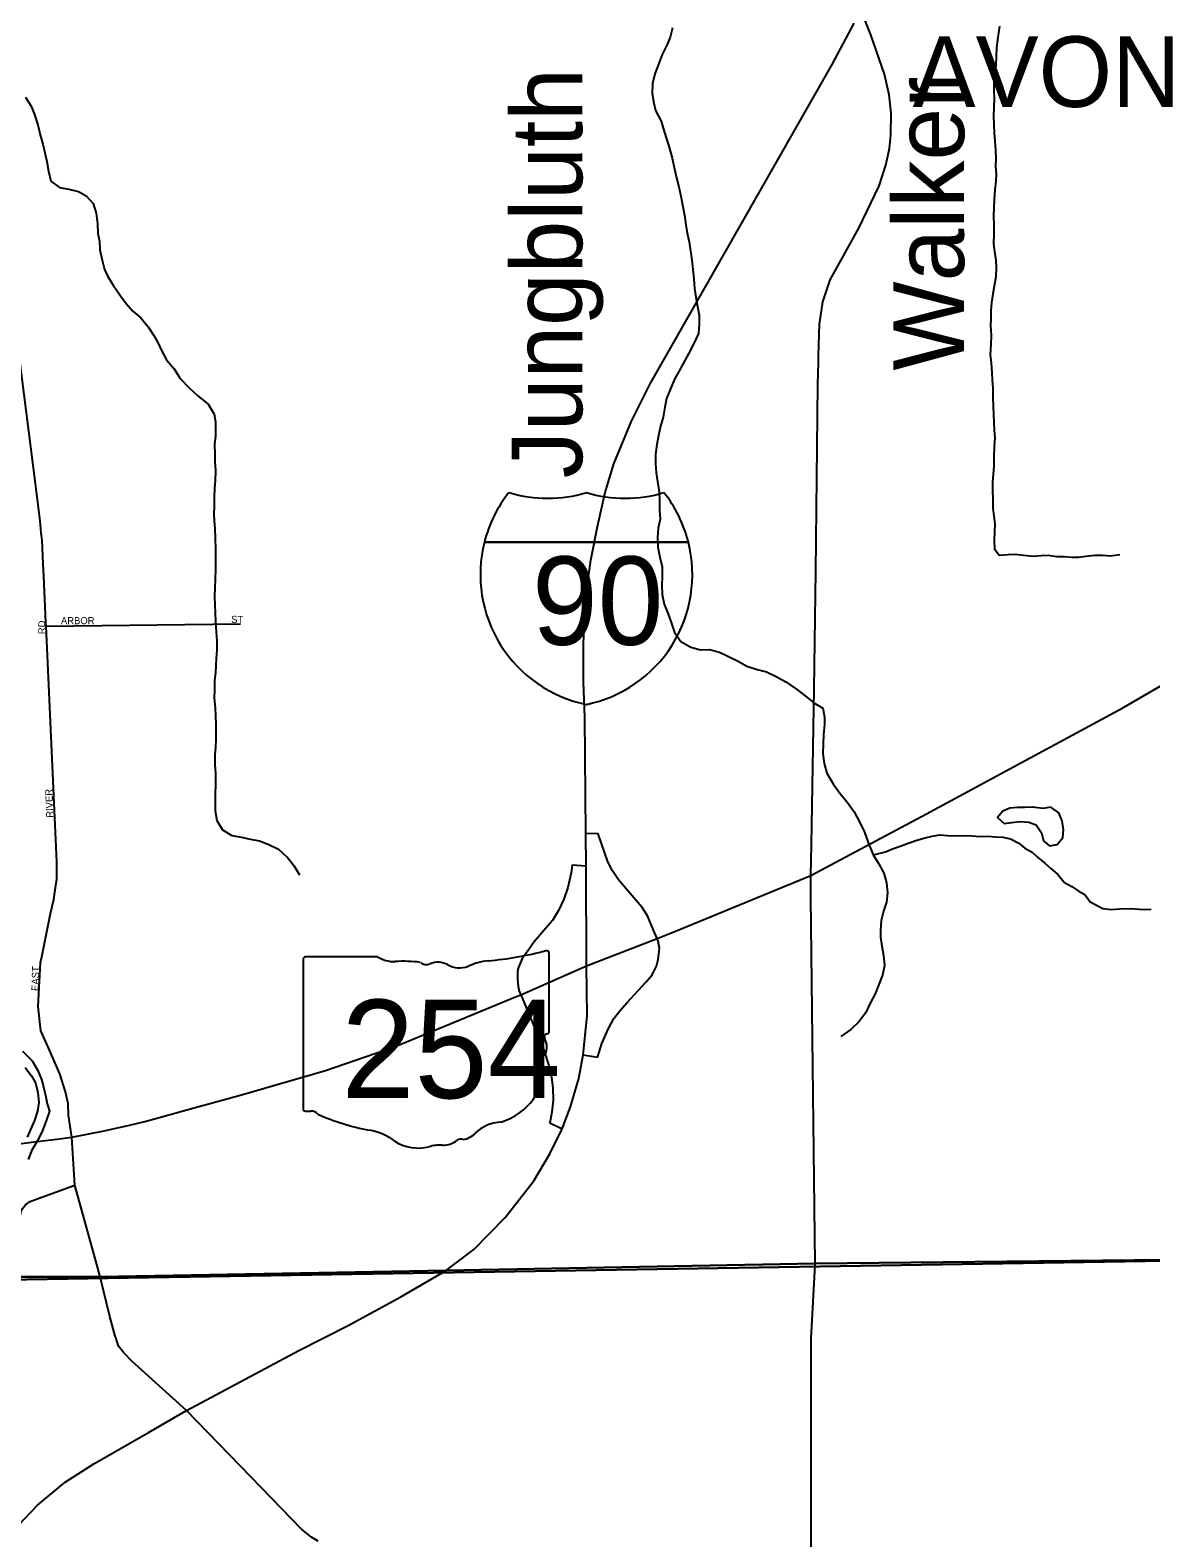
# Model space of a CAD drawing. Extents: x 1857828 to 2277390, y 930619 to 1324581.
# Drawn here: x 2078983 to 2086916, y 1243739 to 1254407 of the extents above; entities that cross this region are included whole.
import ezdxf

# ---------------------------------------------------------------- set-up
doc = ezdxf.new("R2010")
doc.units = 0
for name, color, linetype in [('GM_X_City_Street', 7, 'Continuous'), ('GM_X_City_Street_Text', 7, 'Continuous'), ('GM_X_Corporation', 7, 'Continuous'), ('GM_X_Corporation_Text', 7, 'Continuous'), ('GM_X_Interchange_Ramps', 7, 'Continuous'), ('GM_X_Interstate_Location', 7, 'Continuous'), ('GM_X_Interstate_Route', 7, 'Continuous'), ('GM_X_Interstate_Shield', 7, 'Continuous'), ('GM_X_Major_River', 7, 'Continuous'), ('GM_X_Minor_Lake', 7, 'Continuous'), ('GM_X_Minor_River', 7, 'Continuous'), ('GM_X_Minor_River_Text', 7, 'Continuous'), ('GM_X_State_Location', 7, 'Continuous'), ('GM_X_State_Route', 7, 'Continuous'), ('GM_X_State_Shield', 7, 'Continuous'), ('GM_X_Township', 7, 'Continuous')]:
    doc.layers.add(name, color=color, linetype=linetype)

msp = doc.modelspace()

# ---------------------------------------------------------------- linework, layer by layer
at = {"layer": 'GM_X_City_Street'}
for points in [[(2079066, 1247850), (2079128, 1248157), (2079150, 1248255), (2079156, 1248291), (2079161, 1248323), (2079165, 1248356), (2079171, 1248400), (2079171, 1248522), (2079096, 1250190), (2079094, 1250216), (2079085, 1250435), (2079081, 1250544), (2079076, 1250630), (2079070, 1250742), (2079068, 1250799), (2079061, 1250851), (2079053, 1250935), (2079024, 1251180), (2078679, 1253867)], [(2079096, 1250190), (2080473, 1250206)], [(2079278, 1246575), (2079254, 1246729), (2079251, 1246812), (2079233, 1246894), (2079192, 1247021), (2079113, 1247205), (2079058, 1247327), (2079040, 1247499), (2079057, 1247809), (2079066, 1247850)], [(2079454, 1245674), (2079299, 1246235), (2079278, 1246575)], [(2078772, 1245558), (2078782, 1245586), (2078812, 1245672), (2078854, 1245786), (2078868, 1245830), (2078881, 1245873), (2078898, 1245949), (2078909, 1246005), (2078920, 1246049), (2078928, 1246069), (2078950, 1246095), (2078983, 1246119), (2079033, 1246138), (2079299, 1246235)], [(2079589, 1245157), (2079586, 1245166), (2079546, 1245304), (2079478, 1245586), (2079454, 1245674)], [(2080548, 1244168), (2080090, 1244639), (2079703, 1244989), (2079646, 1245047), (2079609, 1245094), (2079589, 1245157)], [(2081023, 1243715), (2080975, 1243744), (2080904, 1243800), (2080548, 1244168)]]:
    msp.add_lwpolyline(points, dxfattribs=at)
at = {"layer": 'GM_X_Corporation'}
for points in [[(2073290, 1243422), (2073012, 1245464), (2077086, 1245535), (2087019, 1245699)], [(2087019, 1245699), (2077086, 1245535)]]:
    msp.add_lwpolyline(points, dxfattribs=at)
at = {"layer": 'GM_X_Interchange_Ramps'}
for points in [[(2083421, 1247979), (2083402, 1248023), (2083354, 1248141), (2083316, 1248199), (2083270, 1248252), (2083147, 1248396), (2083106, 1248458), (2083072, 1248523), (2083005, 1248721), (2082916, 1248723)], [(2082918, 1248492), (2082819, 1248498), (2082812, 1248444), (2082790, 1248341), (2082761, 1248257), (2082723, 1248179), (2082680, 1248107), (2082620, 1248036), (2082552, 1247956), (2082501, 1247886), (2082466, 1247838), (2082437, 1247770), (2082432, 1247743), (2082433, 1247694), (2082438, 1247639), (2082445, 1247608), (2082456, 1247582)], [(2082898, 1247157), (2082999, 1247140), (2083001, 1247145), (2083031, 1247236), (2083078, 1247342), (2083115, 1247413), (2083157, 1247469), (2083209, 1247528), (2083343, 1247672), (2083386, 1247722), (2083417, 1247785), (2083428, 1247831), (2083434, 1247872), (2083437, 1247910), (2083428, 1247961), (2083421, 1247979)], [(2082456, 1247582), (2082465, 1247559), (2082620, 1247189), (2082655, 1247080), (2082674, 1246997), (2082683, 1246923), (2082686, 1246835), (2082677, 1246750), (2082662, 1246675), (2082748, 1246634)]]:
    msp.add_lwpolyline(points, dxfattribs=at)
at = {"layer": 'GM_X_Interstate_Route'}
for points in [[(2082922, 1247787), (2082918, 1248492), (2082916, 1248723), (2082910, 1249544), (2082901, 1249796), (2082901, 1250038), (2082906, 1250255), (2082925, 1250471), (2082953, 1250657), (2082999, 1250895), (2083054, 1251136), (2083115, 1251339), (2083240, 1251640), (2083373, 1251905), (2084661, 1254164), (2084817, 1254456)], [(2081931, 1245634), (2082123, 1245778), (2082345, 1246005), (2082548, 1246265), (2082662, 1246455), (2082748, 1246634), (2082809, 1246788), (2082866, 1246988), (2082898, 1247157), (2082925, 1247432), (2082922, 1247787)], [(2080090, 1244639), (2080886, 1245065), (2081234, 1245242), (2081606, 1245443), (2081927, 1245631), (2081931, 1245634)], [(2078147, 1242480), (2078285, 1242776), (2078548, 1243357), (2078667, 1243527), (2078771, 1243668), (2078895, 1243824), (2079034, 1243971), (2079230, 1244132), (2079434, 1244263), (2079820, 1244484), (2080090, 1244639)]]:
    msp.add_lwpolyline(points, dxfattribs=at)
at = {"layer": 'GM_X_Interstate_Shield'}
for p, q in [((2082199, 1250785), (2083642, 1250785)), ((2083642, 1250785), (2082199, 1250785)), ((2083642, 1250785), (2082199, 1250785))]:
    msp.add_line(p, q, dxfattribs=at)
for centre, start, end in [((2083108, 1250555), 141.669, 165.8066), ((2082647, 1252033), 253.0091, 286.9909), ((2083195, 1252033), 253.0091, 286.9909), ((2082733, 1250555), 14.1934, 38.331), ((2083108, 1250555), 165.8066, 258.463), ((2082733, 1250555), 281.537, 14.1934)]:
    msp.add_arc(centre, 938, start, end, dxfattribs=at)
at = {"layer": 'GM_X_Major_River'}
for points in [[(2078929, 1247183), (2078998, 1247115), (2079038, 1247046), (2079063, 1246982), (2079077, 1246930), (2079093, 1246860), (2079104, 1246809), (2079120, 1246759), (2079096, 1246689), (2079070, 1246620), (2079038, 1246552), (2078996, 1246481), (2078970, 1246417)], [(2078948, 1247068), (2078992, 1247008), (2079021, 1246958), (2079037, 1246890), (2079045, 1246819), (2079035, 1246759), (2079014, 1246691), (2078986, 1246628), (2078962, 1246574)]]:
    msp.add_lwpolyline(points, dxfattribs=at)
at = {"layer": 'GM_X_Minor_Lake'}
for points in [[(2086077, 1248909), (2086022, 1248906), (2085972, 1248906), (2085918, 1248901), (2085868, 1248880), (2085832, 1248836), (2085877, 1248794), (2085931, 1248801), (2085991, 1248808), (2086053, 1248804), (2086104, 1248785)], [(2086080, 1248909), (2086022, 1248906), (2085972, 1248906), (2085918, 1248901), (2085868, 1248880), (2085832, 1248836), (2085877, 1248794), (2085931, 1248801), (2085991, 1248808), (2086053, 1248804), (2086104, 1248785)], [(2086104, 1248785), (2086143, 1248727), (2086157, 1248671), (2086200, 1248635), (2086254, 1248644), (2086294, 1248694), (2086297, 1248749), (2086288, 1248813), (2086264, 1248869), (2086209, 1248908), (2086155, 1248900), (2086077, 1248909)], [(2086104, 1248785), (2086143, 1248727), (2086157, 1248671), (2086200, 1248635), (2086254, 1248644), (2086294, 1248694), (2086297, 1248749), (2086288, 1248813), (2086264, 1248869), (2086209, 1248908), (2086155, 1248900), (2086077, 1248909)]]:
    msp.add_lwpolyline(points, dxfattribs=at)
at = {"layer": 'GM_X_Minor_River'}
for points in [[(2083531, 1254424), (2083513, 1254357), (2083493, 1254307), (2083457, 1254236), (2083428, 1254160), (2083404, 1254098), (2083388, 1254029), (2083386, 1253959), (2083397, 1253891), (2083411, 1253838), (2083451, 1253764), (2083464, 1253714), (2083508, 1253569), (2083527, 1253501), (2083543, 1253435), (2083559, 1253362), (2083576, 1253298), (2083590, 1253232), (2083600, 1253172), (2083615, 1253099), (2083625, 1253031), (2083635, 1252971), (2083648, 1252909), (2083668, 1252780), (2083681, 1252647), (2083685, 1252579), (2083695, 1252519), (2083706, 1252452), (2083718, 1252390), (2083720, 1252326), (2083714, 1252262), (2083682, 1252191), (2083645, 1252121), (2083573, 1251988), (2083545, 1251937), (2083515, 1251869), (2083487, 1251800), (2083475, 1251740), (2083464, 1251670), (2083446, 1251605), (2083432, 1251539), (2083420, 1251475)], [(2085845, 1254436), (2085830, 1254342), (2085823, 1254281), (2085821, 1254223), (2085818, 1254159), (2085813, 1254090), (2085805, 1254036), (2085804, 1253980), (2085807, 1253925), (2085804, 1253859), (2085802, 1253801), (2085805, 1253738), (2085808, 1253682), (2085812, 1253622), (2085817, 1253556), (2085820, 1253501), (2085817, 1253443), (2085821, 1253389), (2085820, 1253339), (2085813, 1253278), (2085807, 1253210), (2085806, 1253151), (2085803, 1253095), (2085804, 1253025), (2085806, 1252963), (2085803, 1252896), (2085810, 1252842), (2085819, 1252778), (2085821, 1252727), (2085820, 1252663), (2085807, 1252595), (2085797, 1252542), (2085788, 1252480), (2085783, 1252422), (2085783, 1252365), (2085782, 1252315), (2085785, 1252249), (2085784, 1252184), (2085780, 1252110), (2085785, 1252054), (2085790, 1251983), (2085793, 1251931), (2085797, 1251877), (2085798, 1251809), (2085801, 1251742), (2085802, 1251690), (2085804, 1251628), (2085807, 1251577), (2085812, 1251523), (2085808, 1251461), (2085805, 1251386), (2085804, 1251320), (2085799, 1251266), (2085795, 1251212), (2085796, 1251149), (2085797, 1251091), (2085798, 1251025), (2085804, 1250968), (2085811, 1250914), (2085810, 1250860), (2085808, 1250798), (2085809, 1250737), (2085842, 1250693), (2085906, 1250698), (2085956, 1250699), (2086015, 1250693), (2086083, 1250686), (2086139, 1250691), (2086191, 1250693), (2086250, 1250684), (2086304, 1250684), (2086354, 1250679), (2086404, 1250678), (2086457, 1250686)], [(2078951, 1253934), (2078991, 1253870), (2079014, 1253810), (2079038, 1253738), (2079054, 1253667), (2079073, 1253601), (2079089, 1253529), (2079101, 1253477), (2079114, 1253410), (2079130, 1253338), (2079190, 1253294), (2079257, 1253282), (2079325, 1253266), (2079380, 1253236), (2079430, 1253180), (2079450, 1253112), (2079459, 1253038), (2079463, 1252969), (2079475, 1252915), (2079477, 1252853), (2079492, 1252780), (2079510, 1252714), (2079532, 1252664), (2079571, 1252602), (2079623, 1252528), (2079662, 1252473), (2079710, 1252419), (2079767, 1252371), (2079819, 1252309), (2079858, 1252247), (2079886, 1252197), (2079914, 1252141), (2079949, 1252074), (2080003, 1252010), (2080046, 1251942), (2080108, 1251876), (2080171, 1251820), (2080243, 1251760), (2080286, 1251689), (2080296, 1251637), (2080296, 1251587), (2080294, 1251531), (2080288, 1251478), (2080291, 1251408), (2080291, 1251358), (2080295, 1251290), (2080293, 1251221), (2080288, 1251167), (2080286, 1251103), (2080286, 1251036), (2080284, 1250986), (2080285, 1250936), (2080291, 1250881), (2080293, 1250809), (2080295, 1250741), (2080296, 1250592), (2080292, 1250524), (2080290, 1250459), (2080289, 1250403), (2080291, 1250337), (2080293, 1250284), (2080295, 1250218), (2080300, 1250150), (2080304, 1250084), (2080304, 1250019), (2080300, 1249963), (2080297, 1249911), (2080295, 1249860), (2080289, 1249806), (2080287, 1249740), (2080285, 1249683), (2080292, 1249611), (2080294, 1249555), (2080298, 1249491), (2080298, 1249438), (2080297, 1249388), (2080295, 1249332), (2080291, 1249282), (2080291, 1249213), (2080294, 1249145), (2080296, 1249072), (2080292, 1249002), (2080292, 1248950), (2080293, 1248884), (2080305, 1248815), (2080345, 1248749), (2080410, 1248709), (2080480, 1248697), (2080540, 1248683), (2080607, 1248672), (2080673, 1248646), (2080740, 1248612), (2080806, 1248550), (2080849, 1248497)], [(2083420, 1251475), (2083410, 1251408), (2083409, 1251340), (2083415, 1251276), (2083425, 1251213), (2083436, 1251141), (2083438, 1251075), (2083438, 1251008), (2083442, 1250946), (2083428, 1250884), (2083423, 1250817), (2083427, 1250749), (2083441, 1250679), (2083458, 1250610), (2083458, 1250544), (2083454, 1250478), (2083456, 1250414), (2083471, 1250345), (2083497, 1250281), (2083520, 1250215), (2083544, 1250146), (2083588, 1250082), (2083659, 1250042), (2083729, 1250022), (2083789, 1250025), (2083862, 1250007), (2083995, 1249943), (2084057, 1249907), (2084129, 1249883), (2084196, 1249867), (2084264, 1249833), (2084333, 1249795), (2084409, 1249745), (2084470, 1249697), (2084530, 1249647), (2084595, 1249609), (2084605, 1249545), (2084605, 1249495), (2084599, 1249424), (2084596, 1249356), (2084594, 1249290), (2084604, 1249219), (2084623, 1249149), (2084667, 1249075), (2084715, 1249009), (2084768, 1248941), (2084816, 1248876), (2084855, 1248806), (2084889, 1248732), (2084916, 1248660)], [(2086457, 1250686), (2086519, 1250693), (2086577, 1250692), (2086629, 1250688), (2086696, 1250697)], [(2084951, 1248571), (2084971, 1248577), (2085039, 1248592), (2085087, 1248614), (2085149, 1248635), (2085205, 1248656), (2085259, 1248675), (2085319, 1248691), (2085369, 1248704), (2085422, 1248713), (2085478, 1248709), (2085530, 1248706), (2085588, 1248709), (2085651, 1248707), (2085709, 1248702), (2085763, 1248704), (2085816, 1248699), (2085868, 1248698), (2085924, 1248684), (2085981, 1248655), (2086025, 1248619), (2086076, 1248591), (2086113, 1248556), (2086167, 1248512), (2086208, 1248476), (2086255, 1248435), (2086306, 1248377), (2086356, 1248347), (2086401, 1248318), (2086449, 1248290), (2086486, 1248240), (2086531, 1248216), (2086577, 1248191), (2086635, 1248184), (2086694, 1248190), (2086744, 1248193), (2086802, 1248189), (2086869, 1248186), (2086919, 1248187)], [(2084916, 1248660), (2084950, 1248573), (2084991, 1248507), (2085027, 1248441), (2085045, 1248373), (2085052, 1248304), (2085046, 1248236), (2085024, 1248174), (2085008, 1248107), (2085003, 1248039), (2085003, 1247989), (2085011, 1247926), (2085023, 1247860), (2085030, 1247788), (2085016, 1247721), (2084990, 1247655), (2084964, 1247589), (2084930, 1247522), (2084898, 1247456), (2084852, 1247393), (2084792, 1247337), (2084722, 1247286)], [(2080849, 1248497), (2080889, 1248431)]]:
    msp.add_lwpolyline(points, dxfattribs=at)
at = {"layer": 'GM_X_State_Route'}
for points in [[(2084564, 1252105), (2084571, 1252327), (2084594, 1252484), (2084646, 1252640), (2084849, 1253007), (2084993, 1253307), (2085041, 1253451), (2085066, 1253570), (2085076, 1253666), (2085077, 1253821), (2085064, 1253949), (2085030, 1254096), (2084934, 1254375), (2084866, 1254547)], [(2084514, 1248645), (2084532, 1249747), (2084544, 1250580), (2084558, 1251899), (2084563, 1252056), (2084564, 1252105)], [(2085075, 1248727), (2085297, 1248846), (2085882, 1249161), (2086718, 1249611), (2087055, 1249807), (2087086, 1249830)], [(2084510, 1248425), (2085072, 1248726), (2085075, 1248727)], [(2084510, 1248425), (2084514, 1248642), (2084514, 1248645)], [(2083552, 1248032), (2084510, 1248425)], [(2084510, 1248269), (2084510, 1248269), (2084510, 1248425)], [(2084540, 1245669), (2084541, 1245679), (2084510, 1248269)], [(2082407, 1247562), (2082456, 1247582), (2082922, 1247787), (2083421, 1247979), (2083552, 1248032)], [(2082214, 1247483), (2082407, 1247562)], [(2081877, 1247343), (2082214, 1247483)], [(2080040, 1246753), (2080478, 1246874), (2081074, 1247046), (2081566, 1247215), (2081877, 1247343)], [(2079172, 1246561), (2079278, 1246575), (2079506, 1246618), (2079687, 1246660)], [(2079687, 1246660), (2079794, 1246685), (2080000, 1246742), (2080040, 1246753)], [(2079012, 1246541), (2079172, 1246561)], [(2077785, 1246380), (2078363, 1246457), (2079012, 1246541)], [(2084511, 1245150), (2084540, 1245669)], [(2084511, 1242129), (2084511, 1242341), (2084511, 1245149), (2084511, 1245150)]]:
    msp.add_lwpolyline(points, dxfattribs=at)
at = {"layer": 'GM_X_State_Shield'}
for p, q in [((2080916, 1247832), (2080916, 1246775)), ((2081443, 1247850), (2080933, 1247850)), ((2082657, 1247324), (2082657, 1247876)), ((2082656, 1247324), (2082657, 1247324))]:
    msp.add_line(p, q, dxfattribs=at)
for centre, major_axis, start_param, end_param in [((2080936, 1247834), (20.2, 0), 1.712693, 3.28349), ((2081564, 1247973), (196, 0), 4.042523, 4.731795), ((2082037, 1249291), (1845, 0), 4.814394, 5.042369), ((2082637, 1247879), (19.4, 0), 6.141152, 7.989035), ((2081629, 1247257), (702, 0), 1.404758, 1.657858), ((2081789, 1247840), (56.4, 0), 3.836095, 5.185415), ((2081871, 1247718), (117, 0), 0.950623, 2.079405), ((2082023, 1247885), (141, 0), 4.081561, 5.145723), ((2082272, 1247527), (371, 0), 1.699011, 2.107814), ((2082652, 1247283), (30, 0), 1.883978, 3.671073), ((2082636, 1247321), (20.7, 0), 5.05454, 6.418171), ((2082461, 1247213), (180, 0), 5.934695, 6.695948), ((2082140, 1247022), (462, 0), 5.101752, 6.440018), ((2082726, 1247092), (131, 0), 2.387724, 3.262537), ((2080936, 1246773), (20.3, 0), 3.00124, 4.508301), ((2080940, 1246881), (155, 0), 4.665946, 4.897461), ((2080971, 1246714), (56, 0), 0.519207, 1.627899), ((2081678, 1247664), (1333, 0), 4.195997, 4.488961), ((2082335, 1246479), (253, 0), 1.647645, 2.488434), ((2081281, 1246301), (417, 0), 0.823519, 1.323587), ((2081732, 1246709), (265, 0), 4.026481, 4.996735), ((2081904, 1246630), (141, 0), 4.691044, 5.507374), ((2082031, 1246528), (39.7, 0), 1.147584, 2.315152), ((2082014, 1246673), (149, 0), 4.937069, 5.64225), ((2081884, 1246344), (217, 0), 1.495662, 1.94098)]:
    msp.add_ellipse(centre, major_axis=major_axis, ratio=0.8, start_param=start_param, end_param=end_param, dxfattribs=at)
at = {"layer": 'GM_X_Township'}
for points in [[(2078782, 1245586), (2079478, 1245586), (2081927, 1245631), (2084541, 1245679), (2087028, 1245707)], [(2087028, 1245707), (2084541, 1245679), (2081927, 1245631), (2079478, 1245586), (2078782, 1245586)]]:
    msp.add_lwpolyline(points, dxfattribs=at)

# ---------------------------------------------------------------- texts
at = {"layer": 'GM_X_City_Street_Text'}
for s, rotation, p in [('RD', 90, (2079090, 1250133)), ('ARBOR', 0, (2079201, 1250204)), ('ST', 0, (2080406, 1250213)), ('RIVER', 92.2013, (2079147, 1248835)), ('EAST', 88.3645, (2079042, 1247608))]:
    msp.add_text(s, height=50, rotation=rotation, dxfattribs=at).set_placement(p)
at = {"layer": 'GM_X_Corporation_Text'}
msp.add_text('AVON', height=500, rotation=0, dxfattribs=at).set_placement((2085230, 1253864))
at = {"layer": 'GM_X_Interstate_Location'}
for s in ['.', '-', ',']:
    msp.add_text(s, height=1, dxfattribs=at).set_placement((2082921, 1250386))
msp.add_text('90', height=1, rotation=0, dxfattribs=at).set_placement((2082716, 1250179))
at = {"layer": 'GM_X_Interstate_Shield'}
msp.add_text('90', height=625, dxfattribs=at).set_placement((2082536, 1250058))
at = {"layer": 'GM_X_Minor_River_Text'}
for s, rotation, p in [('Jungbluth', 89.9923, (2082891, 1251236)), ('Walker', 89.992, (2085594, 1251998))]:
    msp.add_text(s, height=500.4, rotation=rotation, dxfattribs=at).set_placement(p)
at = {"layer": 'GM_X_State_Location'}
for s in ['s', 'r']:
    msp.add_text(s, height=1, dxfattribs=at).set_placement((2081767, 1247233))
msp.add_text('254', height=1, rotation=0, dxfattribs=at).set_placement((2081414, 1247161))
at = {"layer": 'GM_X_State_Shield'}
msp.add_text('254', height=696.1, dxfattribs=at).set_placement((2081186, 1246850))

doc.saveas('drawing.dxf')
